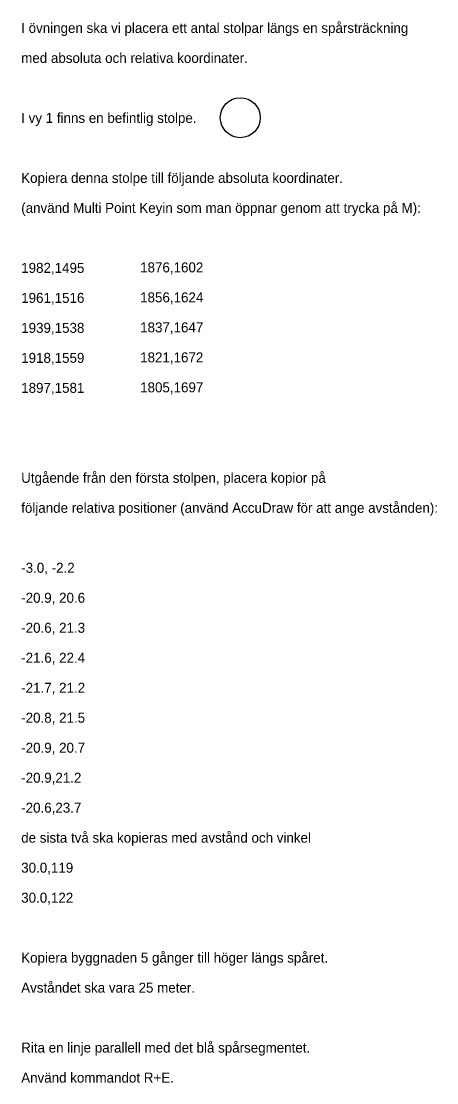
# Model space of a CAD drawing. Extents: x 1715 to 2313, y 1461 to 1736.
# Drawn here: x 2302.91 to 2313.31, y 1709.07 to 1735.61 of the extents above; entities that cross this region are included whole.
import ezdxf

# ---------------------------------------------------------------- set-up
doc = ezdxf.new("R2010")
doc.units = 0
doc.layers.add('Instruktioner', color=7, linetype='Continuous')

msp = doc.modelspace()

# ---------------------------------------------------------------- linework, layer by layer
at = {"layer": 'Instruktioner'}
msp.add_circle((2308.393, 1733.201), 0.5, dxfattribs=at)

# ---------------------------------------------------------------- texts
for s, p in [('I övningen ska vi placera ett antal stolpar längs en spårsträckning', (2302.913, 1735.32)), ('med absoluta och relativa koordinater.', (2302.913, 1734.57)), ('I vy 1 finns en befintlig stolpe.', (2302.913, 1733.07)), ('Kopiera denna stolpe till följande absoluta koordinater.', (2302.913, 1731.57)), ('(använd Multi Point Keyin som man öppnar genom att trycka på M):', (2302.913, 1730.82)), ('1982,1495', (2302.913, 1729.32)), ('1876,1602', (2305.888, 1729.332)), ('1961,1516', (2302.913, 1728.57)), ('1856,1624', (2305.888, 1728.582)), ('1939,1538', (2302.913, 1727.82)), ('1837,1647', (2305.888, 1727.832)), ('1918,1559', (2302.913, 1727.07)), ('1821,1672', (2305.888, 1727.082)), ('1805,1697', (2305.888, 1726.332)), ('1897,1581', (2302.913, 1726.32)), ('Utgående från den första stolpen, placera kopior på', (2302.913, 1724.07)), ('följande relativa positioner (använd AccuDraw för att ange avstånden):', (2302.913, 1723.32)), ('-3.0, -2.2', (2302.913, 1721.82)), ('-20.9, 20.6', (2302.913, 1721.07)), ('-20.6, 21.3', (2302.913, 1720.32)), ('-21.6, 22.4', (2302.913, 1719.57)), ('-21.7, 21.2', (2302.913, 1718.82)), ('-20.8, 21.5', (2302.913, 1718.07)), ('-20.9, 20.7', (2302.913, 1717.32)), ('-20.9,21.2', (2302.913, 1716.57)), ('-20.6,23.7', (2302.913, 1715.82)), ('de sista två ska kopieras med avstånd och vinkel', (2302.913, 1715.07)), ('30.0,119', (2302.913, 1714.32)), ('30.0,122', (2302.913, 1713.57)), ('Kopiera byggnaden 5 gånger till höger längs spåret.', (2302.913, 1712.07)), ('Avståndet ska vara 25 meter.', (2302.913, 1711.32)), ('Rita en linje parallell med det blå spårsegmentet.', (2302.913, 1709.82)), ('Använd kommandot R+E.', (2302.913, 1709.07))]:
    msp.add_text(s, height=0.25, dxfattribs=at).set_placement(p)

doc.saveas('drawing.dxf')
